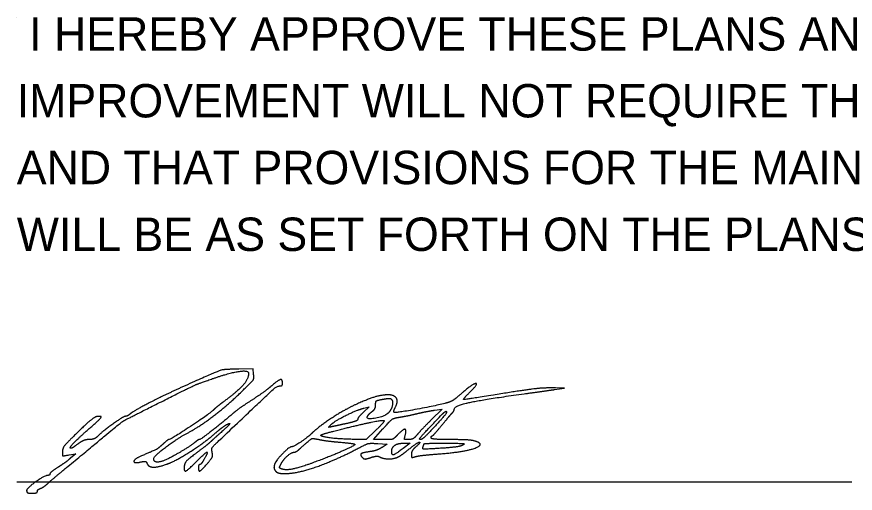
# Model space of a CAD drawing. Extents: x 0 to 34, y 0 to 22.
# Drawn here: x 24.528 to 28.042, y 8.879 to 10.877 of the extents above; entities that cross this region are included whole.
import ezdxf

# ---------------------------------------------------------------- set-up
doc = ezdxf.new("R2010")
doc.units = 0
doc.layers.add('SH_Data', color=7, linetype='Continuous')
doc.layers.add('SH_Text', color=7, linetype='Continuous')

msp = doc.modelspace()

# ---------------------------------------------------------------- linework, layer by layer
at = {"layer": 'SH_Data'}
for p, q in [((24.5279, 10.875), (24.5279, 10.875)), ((24.5279, 10.875), (24.5279, 10.875)), ((24.5279, 8.9262), (28.0279, 8.9262))]:
    msp.add_line(p, q, dxfattribs=at)
at = {"layer": 'SH_Text'}
msp.add_line((24.5693, 8.8891), (24.5693, 8.8891), dxfattribs=at)
for points in [[(25.5205, 9.3784), (25.518, 9.4002), (25.458, 9.3995)], [(26.7818, 9.3137), (26.823, 9.3195), (26.7853, 9.3205)], [(25.9831, 9.2356), (26.0055, 9.2409), (25.9812, 9.2186)], [(26.2781, 9.2271), (26.3106, 9.2318), (26.2668, 9.1885)], [(26.0316, 9.1419), (25.9924, 9.104), (25.9389, 9.1049)], [(26.0643, 9.104), (26.0234, 9.104), (26.0626, 9.1485)], [(26.0409, 9.0875), (26.0801, 9.0852), (26.0587, 9.0712)], [(26.1518, 9.089), (26.177, 9.089), (26.1475, 9.0667)], [(24.7474, 9.0398), (24.7755, 9.0447), (24.753, 9.0259)]]:
    msp.add_lwpolyline(points, dxfattribs=at)
for points in [[(25.458, 9.3995), (25.3955, 9.3988), (25.3691, 9.3906), (25.233, 9.3295)], [(25.3605, 9.3634), (25.4246, 9.3853), (25.4993, 9.3953), (25.4993, 9.382)], [(25.1505, 9.2712), (25.2627, 9.3275), (25.2883, 9.3388), (25.3605, 9.3634)], [(25.4993, 9.382), (25.4993, 9.3581), (25.4543, 9.3067), (25.3951, 9.2632)], [(25.4605, 9.2959), (25.5145, 9.3482), (25.5227, 9.3595), (25.5205, 9.3784)], [(25.6418, 9.3402), (25.6418, 9.3582), (25.6242, 9.3533), (25.5925, 9.3265)], [(25.233, 9.3295), (25.1528, 9.2934), (25.017, 9.2238), (25.0037, 9.212)], [(25.3754, 9.0998), (25.5968, 9.3094), (25.6188, 9.3289), (25.6324, 9.3289)], [(25.5925, 9.3265), (25.5763, 9.3128), (25.5394, 9.2864), (25.5105, 9.2677)], [(25.6324, 9.3289), (25.6376, 9.3289), (25.6418, 9.334), (25.6418, 9.3402)], [(26.4286, 9.3046), (26.4654, 9.3414), (26.4359, 9.3361), (26.3929, 9.2981)], [(26.7853, 9.3205), (26.7409, 9.3216), (26.657, 9.312), (26.5253, 9.2906)], [(26.6551, 9.2961), (26.7021, 9.3026), (26.7591, 9.3105), (26.7818, 9.3137)], [(25.2372, 9.128), (25.2909, 9.1564), (25.4056, 9.2426), (25.4605, 9.2959)], [(26.0844, 9.2915), (26.0569, 9.2915), (25.9951, 9.2723), (25.9396, 9.2466)], [(26.1144, 9.2392), (26.1272, 9.2631), (26.1109, 9.2915), (26.0844, 9.2915)], [(26.3929, 9.2981), (26.3737, 9.2812), (26.3513, 9.2648), (26.343, 9.2618)], [(26.3618, 9.2311), (26.3618, 9.2455), (26.4844, 9.2727), (26.6551, 9.2961)], [(26.5253, 9.2906), (26.4049, 9.2711), (26.3963, 9.2723), (26.4286, 9.3046)], [(24.7418, 8.991), (24.9664, 9.177), (24.9759, 9.1835), (25.1505, 9.2712)], [(25.3951, 9.2632), (25.3802, 9.2522), (25.3621, 9.2373), (25.3548, 9.2301)], [(25.5105, 9.2677), (25.4817, 9.2491), (25.4479, 9.2251), (25.4355, 9.2145)], [(25.9396, 9.2466), (25.8976, 9.2272), (25.7891, 9.1548), (25.7634, 9.1291)], [(26.0182, 9.2225), (26.0257, 9.2279), (26.0318, 9.2401), (26.0318, 9.2497)], [(26.0318, 9.2497), (26.0318, 9.2632), (26.0371, 9.2681), (26.0552, 9.2718)], [(26.0552, 9.2718), (26.0681, 9.2743), (26.0833, 9.2765), (26.089, 9.2765)], [(26.089, 9.2765), (26.104, 9.2765), (26.102, 9.2337), (26.0862, 9.217)], [(26.343, 9.2618), (26.3157, 9.2517), (26.1139, 9.2143), (26.1097, 9.2185)], [(25.0037, 9.212), (24.9972, 9.2062), (24.9886, 9.2015), (24.9846, 9.2015)], [(25.3548, 9.2301), (25.34, 9.2152), (25.1732, 9.104), (25.1659, 9.104)], [(25.4355, 9.2145), (25.3909, 9.1761), (25.2982, 9.104), (25.2935, 9.104)], [(25.8443, 9.1662), (25.8587, 9.1811), (25.9538, 9.2286), (25.9831, 9.2356)], [(25.9812, 9.2186), (25.9678, 9.2064), (25.9568, 9.193), (25.9568, 9.1888)], [(26.0862, 9.217), (26.0698, 9.1997), (25.9888, 9.1863), (25.9985, 9.2025)], [(25.9985, 9.2025), (26.0019, 9.2081), (26.0107, 9.2171), (26.0182, 9.2225)], [(26.1097, 9.2185), (26.1074, 9.2208), (26.1096, 9.2301), (26.1144, 9.2392)], [(26.1324, 9.1979), (26.1493, 9.2005), (26.1816, 9.2071), (26.2043, 9.2126)], [(26.2043, 9.2126), (26.227, 9.218), (26.2602, 9.2245), (26.2781, 9.2271)], [(26.3288, 9.222), (26.3322, 9.2185), (26.3084, 9.1895), (26.2558, 9.1331)], [(26.3042, 9.2034), (26.3158, 9.2155), (26.3268, 9.2239), (26.3288, 9.222)], [(26.3093, 9.164), (26.3278, 9.1866), (26.3472, 9.2097), (26.3524, 9.2151)], [(26.3524, 9.2151), (26.3576, 9.2206), (26.3618, 9.2277), (26.3618, 9.2311)], [(24.8621, 9.2001), (24.8541, 9.1988), (24.8186, 9.1694), (24.7834, 9.1349)], [(24.8524, 9.1685), (24.8801, 9.1927), (24.8835, 9.2036), (24.8621, 9.2001)], [(24.9846, 9.2015), (24.9759, 9.2015), (24.8862, 9.1376), (24.8671, 9.1179)], [(25.9137, 9.172), (25.8899, 9.1669), (25.8621, 9.1608), (25.8518, 9.1586)], [(25.8571, 9.1396), (25.9539, 9.1644), (26.0634, 9.1873), (26.0672, 9.1835)], [(25.9568, 9.1888), (25.9568, 9.1847), (25.9374, 9.1771), (25.9137, 9.172)], [(26.0672, 9.1835), (26.0692, 9.1816), (26.0531, 9.1628), (26.0316, 9.1419)], [(26.0626, 9.1485), (26.095, 9.1853), (26.1072, 9.1939), (26.1324, 9.1979)], [(26.2668, 9.1885), (26.2428, 9.1646), (26.2155, 9.1359), (26.2062, 9.1245)], [(26.2196, 9.104), (26.2118, 9.104), (26.2332, 9.1291), (26.3042, 9.2034)], [(24.7524, 9.0683), (24.7487, 9.072), (24.7956, 9.119), (24.8524, 9.1685)], [(25.3643, 9.1342), (25.3787, 9.1469), (25.3969, 9.1608), (25.4046, 9.1651)], [(25.4046, 9.1651), (25.4253, 9.1767), (25.4127, 9.159), (25.3802, 9.1307)], [(25.8022, 9.121), (25.8002, 9.123), (25.8249, 9.1314), (25.8571, 9.1396)], [(25.8518, 9.1586), (25.835, 9.155), (25.8342, 9.1558), (25.8443, 9.1662)], [(26.1562, 9.1227), (26.1624, 9.1474), (26.1464, 9.1474), (26.1229, 9.1226)], [(26.2699, 9.1202), (26.273, 9.1216), (26.2907, 9.1413), (26.3093, 9.164)], [(24.7834, 9.1349), (24.737, 9.0894), (24.7193, 9.0669), (24.7193, 9.0534)], [(24.831, 9.104), (24.818, 9.104), (24.7972, 9.0955), (24.7823, 9.0842)], [(24.8671, 9.1179), (24.8597, 9.1102), (24.8435, 9.104), (24.831, 9.104)], [(25.1018, 9.024), (25.1018, 9.0335), (25.1976, 9.1071), (25.2372, 9.128)], [(25.1659, 9.104), (25.1633, 9.104), (25.152, 9.0955), (25.1409, 9.0852)], [(25.155, 9.0002), (25.1921, 9.013), (25.3186, 9.094), (25.3643, 9.1342)], [(25.2935, 9.104), (25.2908, 9.104), (25.2846, 9.1005), (25.2796, 9.0963)], [(25.3802, 9.1307), (25.3656, 9.1181), (25.348, 9.1022), (25.3411, 9.0955)], [(25.7634, 9.1291), (25.7481, 9.1138), (25.6888, 9.074), (25.6813, 9.074)], [(25.7135, 9.0647), (25.7577, 9.1049), (25.7686, 9.11), (25.7974, 9.1038)], [(25.7974, 9.1038), (25.8129, 9.1005), (25.8537, 9.0954), (25.8881, 9.0925)], [(25.9389, 9.1049), (25.8837, 9.1059), (25.8085, 9.1147), (25.8022, 9.121)], [(26.1229, 9.1226), (26.1083, 9.1072), (26.0981, 9.104), (26.0643, 9.104)], [(26.1704, 9.104), (26.154, 9.104), (26.1521, 9.1064), (26.1562, 9.1227)], [(26.2062, 9.1245), (26.1959, 9.112), (26.182, 9.104), (26.1704, 9.104)], [(26.2558, 9.1331), (26.2408, 9.1171), (26.2245, 9.104), (26.2196, 9.104)], [(26.2643, 9.1108), (26.2643, 9.1146), (26.2668, 9.1188), (26.2699, 9.1202)], [(26.3449, 9.1038), (26.3006, 9.1039), (26.2643, 9.107), (26.2643, 9.1108)], [(26.4427, 9.0991), (26.4333, 9.1017), (26.3893, 9.1038), (26.3449, 9.1038)], [(24.7823, 9.0842), (24.7681, 9.0733), (24.7546, 9.0661), (24.7524, 9.0683)], [(25.1409, 9.0852), (25.1217, 9.0674), (25.1072, 9.0594), (25.0512, 9.0356)], [(25.2796, 9.0963), (25.265, 9.084), (25.2172, 9.0535), (25.1804, 9.033)], [(25.3411, 9.0955), (25.3342, 9.0888), (25.3097, 9.0693), (25.2867, 9.0523)], [(25.347, 9.0502), (25.3441, 9.0655), (25.3498, 9.0755), (25.3754, 9.0998)], [(25.6813, 9.074), (25.6704, 9.074), (25.6133, 9.0155), (25.608, 8.9989)], [(25.6524, 8.9615), (25.702, 8.9615), (25.8613, 9.0165), (25.9586, 9.0673)], [(25.9443, 9.0819), (25.9348, 9.0738), (25.8329, 9.03), (25.7693, 9.0066)], [(25.8881, 9.0925), (25.9225, 9.0896), (25.9478, 9.0849), (25.9443, 9.0819)], [(25.9586, 9.0673), (25.9934, 9.0855), (26.0091, 9.0893), (26.0409, 9.0875)], [(26.0587, 9.0712), (26.0469, 9.0635), (26.0241, 9.0555), (26.0081, 9.0533)], [(26.0993, 9.054), (26.0993, 9.0714), (26.1257, 9.089), (26.1518, 9.089)], [(26.1475, 9.0667), (26.1155, 9.0425), (26.0993, 9.0382), (26.0993, 9.054)], [(26.1728, 9.0645), (26.2054, 9.0909), (26.2247, 9.0955), (26.1968, 9.0702)], [(26.1968, 9.0702), (26.1886, 9.0628), (26.1818, 9.05), (26.1818, 9.0419)], [(26.3045, 9.0674), (26.241, 9.0634), (26.2273, 9.0644), (26.2304, 9.0726)], [(26.2304, 9.0726), (26.2326, 9.0781), (26.2343, 9.0841), (26.2343, 9.0858)], [(26.2343, 9.0858), (26.2343, 9.0875), (26.2739, 9.0888), (26.3224, 9.0887)], [(26.2943, 9.0436), (26.4055, 9.0522), (26.4942, 9.0854), (26.4427, 9.0991)], [(26.3965, 9.0804), (26.3888, 9.0759), (26.3474, 9.07), (26.3045, 9.0674)], [(26.3224, 9.0887), (26.3895, 9.0885), (26.4072, 9.0865), (26.3965, 9.0804)], [(24.7193, 9.0534), (24.7193, 9.036), (24.7211, 9.0351), (24.7474, 9.0398)], [(25.0512, 9.0356), (25.0199, 9.0224), (25.0178, 9.0033), (25.0483, 9.01)], [(25.1804, 9.033), (25.1433, 9.0123), (25.1018, 9.0075), (25.1018, 9.024)], [(25.2867, 9.0523), (25.2468, 9.0228), (25.2293, 9.0021), (25.2293, 8.9844)], [(25.2792, 9.0102), (25.3176, 9.0491), (25.3317, 9.0538), (25.3133, 9.0215)], [(25.3267, 9.0037), (25.3443, 9.0238), (25.3497, 9.0361), (25.347, 9.0502)], [(25.6353, 9.0014), (25.645, 9.0202), (25.6793, 9.0508), (25.691, 9.0512)], [(25.691, 9.0512), (25.6954, 9.0513), (25.7055, 9.0574), (25.7135, 9.0647)], [(26.0081, 9.0533), (25.9766, 9.0491), (25.9656, 9.0397), (25.9778, 9.0275)], [(26.0122, 9.0287), (26.0269, 9.0335), (26.0429, 9.0351), (26.0476, 9.0322)], [(26.0476, 9.0322), (26.0617, 9.0235), (26.1094, 9.0227), (26.1255, 9.0309)], [(26.1255, 9.0309), (26.1338, 9.035), (26.1551, 9.0502), (26.1728, 9.0645)], [(26.1818, 9.0419), (26.1818, 9.0301), (26.1851, 9.0282), (26.1987, 9.0324)], [(26.1987, 9.0324), (26.2079, 9.0352), (26.251, 9.0403), (26.2943, 9.0436)], [(24.753, 9.0259), (24.7407, 9.0155), (24.7162, 8.9978), (24.6987, 8.9865)], [(25.0483, 9.01), (25.064, 9.0134), (25.0711, 9.0116), (25.0744, 9.0031)], [(25.0744, 9.0031), (25.0798, 8.989), (25.1185, 8.9877), (25.155, 9.0002)], [(25.2293, 8.9844), (25.2293, 8.9683), (25.2468, 8.9773), (25.2792, 9.0102)], [(25.2893, 8.9877), (25.2893, 8.9695), (25.3011, 8.9746), (25.3267, 9.0037)], [(25.2949, 8.999), (25.2918, 8.999), (25.2893, 8.9939), (25.2893, 8.9877)], [(25.3133, 9.0215), (25.3063, 9.0091), (25.298, 8.999), (25.2949, 8.999)], [(25.608, 8.9989), (25.6053, 8.9903), (25.6071, 8.9783), (25.6121, 8.9723)], [(25.6362, 8.9813), (25.6291, 8.9842), (25.6289, 8.989), (25.6353, 9.0014)], [(25.7693, 9.0066), (25.712, 8.9856), (25.653, 8.9744), (25.6362, 8.9813)], [(25.9778, 9.0275), (25.983, 9.0223), (25.994, 9.0227), (26.0122, 9.0287)], [(24.6593, 8.9212), (24.6696, 8.9306), (24.7067, 8.962), (24.7418, 8.991)], [(24.6987, 8.9865), (24.6811, 8.9752), (24.6668, 8.9633), (24.6668, 8.96)], [(25.6121, 8.9723), (25.6173, 8.966), (25.6342, 8.9615), (25.6524, 8.9615)], [(24.6592, 8.954), (24.645, 8.954), (24.5693, 8.8994), (24.5693, 8.8891)], [(24.6668, 8.96), (24.6668, 8.9567), (24.6634, 8.954), (24.6592, 8.954)], [(24.6143, 8.8867), (24.6143, 8.8909), (24.6202, 8.8966), (24.6274, 8.8993)], [(24.6274, 8.8993), (24.6346, 8.902), (24.649, 8.9119), (24.6593, 8.9212)], [(24.5693, 8.8891), (24.5693, 8.8828), (24.5778, 8.879), (24.5918, 8.879)], [(24.5918, 8.879), (24.6042, 8.879), (24.6143, 8.8824), (24.6143, 8.8867)]]:
    msp.add_open_spline(points, degree=2, dxfattribs=at)

# ---------------------------------------------------------------- texts
at = {"layer": 'SH_Data'}
for s, p in [(' I HEREBY APPROVE THESE PLANS AND DECLARE THAT THE MAKING OF THIS', (24.5279, 10.735)), ('IMPROVEMENT WILL NOT REQUIRE THE CLOSING TO TRAFFIC OF THE HIGHWAY', (24.5279, 10.455)), ('AND THAT PROVISIONS FOR THE MAINTENANCE AND SAFETY OF TRAFFIC', (24.5279, 10.175)), ('WILL BE AS SET FORTH ON THE PLANS AND ESTIMATES.', (24.5279, 9.895))]:
    msp.add_text(s, height=0.14, dxfattribs=at).set_placement(p)

doc.saveas('drawing.dxf')
